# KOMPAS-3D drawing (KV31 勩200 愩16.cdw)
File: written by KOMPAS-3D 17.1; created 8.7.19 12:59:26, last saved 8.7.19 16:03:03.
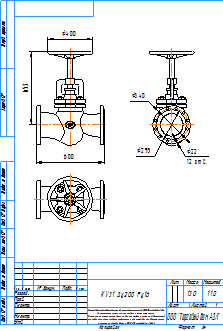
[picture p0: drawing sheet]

Sheet 1: A4, portrait

Title block, sheet 1: name: KV31 Ду200 Ру16; material: Сталь 10  ГОСТ 1050-88; mass: 130; sheets: 1; sheet format: A4

Views: Вид 1, Проекционный вид 2, Проекционный вид 3
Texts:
  kka
  adl
  Рама для чертежей
  Лит-Масса-Масштаб
  Материал-Предприятие
  Масштаб
  Изм.
  Лист
  № докум.
  Подп.
  Дата
  Лит.
  Разраб.
  Пров.
  Т.контр.
  Листов
  Внимание! Данный продукт является объектом авторского права ООО «Торговый Дом АДЛ».
  Запрещается изменение, копирование, распространение
  (в том числе путем копирования на другие сайты и ресурсы в Интернете)
  или любое иное использование информации и объектов без предварительного
  согласия правообладателя (ООО «Торговый Дом АДЛ»).
  Н.контр.
  Утв.
  ООО "Торговый дом АДЛ"
  Изменение
  Номер документа
  Подпись
  Обозначение документа
  Наименование изделия
  Масса изделия по ГОСТ 2.109-73
  Порядковый номер листа
  Общее количество листов в документе
  Характер работы, выполненной лицом, подписавшим документ
  Наименование или индекс предприятия, выпускающего документ
  Инв. № подл.
  Подп. и дата
  Взам. инв. №
  Инв. № дубл.
  Инвентарный номер подлинника по ГОСТ 2.501-68
  Подпись принявшего подлинник в отдел технической документации
  Инвентарный номер подлинника, взамен которого выпущен данный подлинник
  Инвентарный номер дубликата по ГОСТ 2.502-68
  Подпись принявшего дубликат в отдел технической документации
  Справ. №
  Перв. примен.
  Обозначение документа, взамен или на основании которого выпущен данный документ
  Обозначение документа, в котором впервые записан данный документ
  Подпись лица, копировавшего чертеж
  Обозначение формата листа
  !Рама для чертежа
Dimensions and other numbers on the sheet: 600; 653; 400; 295; 22; 12 отв.; 340; 1:10; 1; 130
